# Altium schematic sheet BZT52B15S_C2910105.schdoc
size 127 x 101 mm
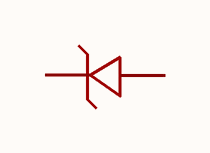
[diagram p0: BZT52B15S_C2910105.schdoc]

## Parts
D?  bzt52b15s_c2910105  [SOD-323_L1.8-W1.3-LS2.5-RD]  (value not drawn)

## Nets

Not connected (* = marked no-connect by the designer): D? 1(C) 2(A)

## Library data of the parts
D? = bzt52b15s_c2910105: 二极管配置:1个独立式;稳压值(标称值):15V;稳压值(范围):14.7V~15.3V;耗散功率(Pd):200mW;; Manufacturer: CJ(江苏长电/长晶); AddInBom: yes; ModelId: db63db13d9e342eb939127d413d6200b; ModelTransform: 104.3305,51.181,0,0,0,0,0,-0.004,0; Diode Configuration: 1个独立式; Zener Voltage(Nom): 15V; Reverse Leakage Current (Ir): 100nA; Pd - Power Dissipation: 200mW; Impedance(Zzt): 30Ω; Impedance(Zzk): 200Ω; Operating Junction Temperature Range: -55℃~+150℃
